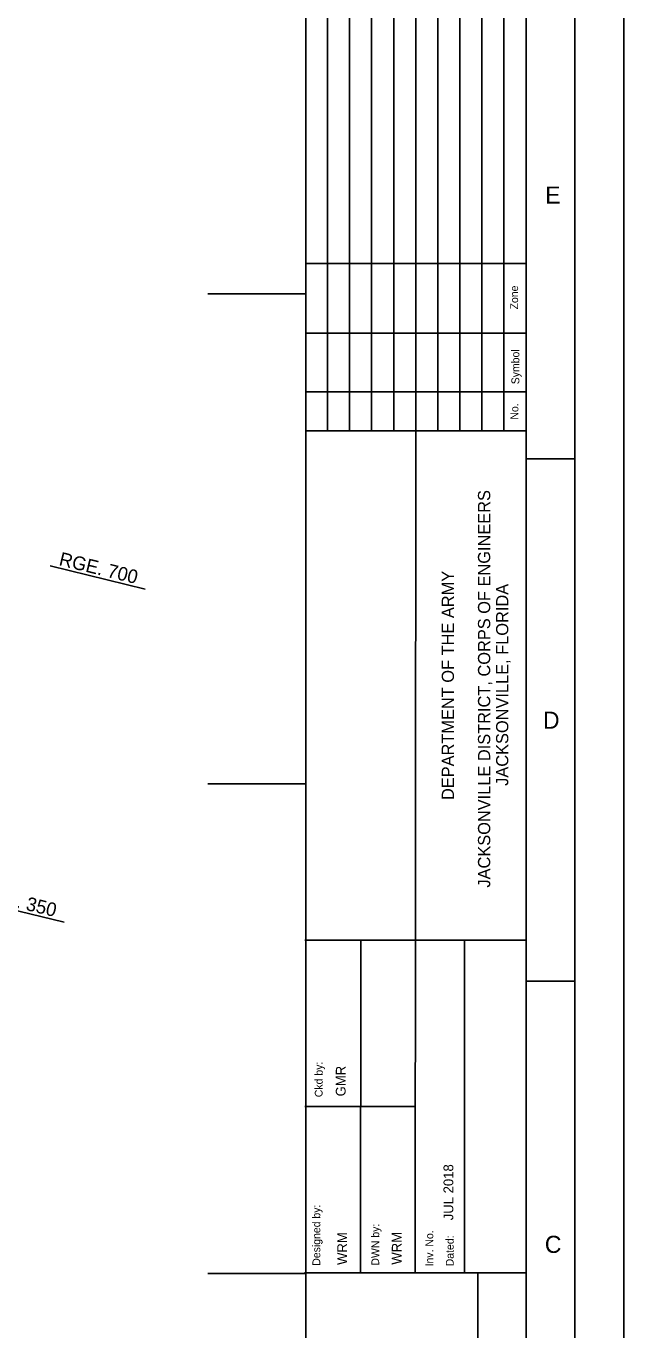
# Model space of a CAD drawing. Extents: x 401290 to 405690, y 1190598 to 1193998.
# Drawn here: x 405079 to 405690, y 1191942 to 1193274 of the extents above; entities that cross this region are included whole.
import ezdxf

# ---------------------------------------------------------------- set-up
doc = ezdxf.new("R2010")
doc.units = 0
for name, color, linetype in [('G-ANNO-NPLT', 7, 'Continuous'), ('G-ANNO-TEXT-DRWG', 7, 'Continuous'), ('G-ANNO-TEXT-PROJ', 7, 'Continuous'), ('G-ANNO-TEXT-TTLB', 7, 'Continuous'), ('G-ANNO-TTLB', 7, 'Continuous'), ('V-ALGN-TEXT', 7, 'Continuous'), ('V-TOPO-COOR-STAT', 7, 'Continuous')]:
    doc.layers.add(name, color=color, linetype=linetype)

msp = doc.modelspace()

# ---------------------------------------------------------------- linework, layer by layer
at = {"layer": 'G-ANNO-NPLT'}
msp.add_lwpolyline([(401290, 1193998.4), (405690, 1193998.4), (405690, 1190598.4), (401290, 1190598.4)], close=True, dxfattribs=at)
at = {"layer": 'G-ANNO-TTLB'}
for p, q in [((405365, 1193898.4), (405365, 1190698.4)), ((405387.3, 1193698.1), (405387.3, 1192860.1)), ((405409.8, 1193698.1), (405409.8, 1192860.1)), ((405432.3, 1193698.1), (405432.3, 1192860.1)), ((405454.8, 1193698.1), (405454.8, 1192860.1)), ((405477.3, 1193698.1), (405477.3, 1192860.1)), ((405499.8, 1193698.1), (405499.8, 1192860.1)), ((405522.3, 1193698.1), (405522.3, 1192860.1)), ((405544.8, 1193698.1), (405544.8, 1192860.1)), ((405567.3, 1193698.1), (405567.3, 1192860.1)), ((405365, 1193031.2), (405590, 1193031.2)), ((405365, 1192960), (405590, 1192960)), ((405365, 1192900), (405590, 1192900)), ((405365, 1192860.1), (405590, 1192860.1)), ((405476.8, 1192000.6), (405477.5, 1192860.1)), ((405477.5, 1192860.1), (405477.5, 1192824.7)), ((405640, 1192831.6), (405590, 1192831.6)), ((405364.2, 1192340.2), (405590, 1192340.2)), ((405420.9, 1192000.6), (405421.1, 1192340.2)), ((405527, 1192340.2), (405527, 1192000.6)), ((405640, 1192298.3), (405590, 1192298.3)), ((405364.2, 1192170.4), (405477, 1192170.4)), ((405363.8, 1192000.6), (405590, 1192000.6)), ((405540.7, 1192000.6), (405540.7, 1191649.2))]:
    msp.add_line(p, q, dxfattribs=at)
for points in [[(401340, 1190648.4), (405640, 1190648.4), (405640, 1193948.4), (401340, 1193948.4)], [(405590, 1193898.4), (401465, 1193898.4), (401465, 1190698.4), (405590, 1190698.4)]]:
    msp.add_lwpolyline(points, close=True, dxfattribs=at)
at = {"layer": 'V-ALGN-TEXT'}
for p, q in [((405103.9, 1192722.4), (405201, 1192698.7)), ((405020.9, 1192382.3), (405118.1, 1192358.6))]:
    msp.add_line(p, q, dxfattribs=at)
at = {"layer": 'V-TOPO-COOR-STAT'}
for p, q in [((405265, 1193000), (405365, 1193000)), ((405265, 1192500), (405365, 1192500)), ((405265, 1192000), (405365, 1192000))]:
    msp.add_line(p, q, dxfattribs=at)

# ---------------------------------------------------------------- texts
at = {"layer": 'G-ANNO-TEXT-DRWG'}
for s, p in [('GMR', (405405.7, 1192180.7)), ('WRM', (405407.2, 1192008.6)), ('WRM', (405462.9, 1192008.9))]:
    msp.add_text(s, height=10, rotation=90, dxfattribs=at).set_placement(p)
at = {"layer": 'G-ANNO-TEXT-PROJ'}
msp.add_text('JUL 2018', height=10, rotation=90, dxfattribs=at).set_placement((405515.7, 1192054.2))
at = {"layer": 'G-ANNO-TEXT-TTLB'}
for s, height, p in [('Zone', 8, (405581.9, 1192984.2)), ('Symbol', 8, (405583.1, 1192907.8)), ('No.', 8, (405582.1, 1192871.7)), ('JACKSONVILLE DISTRICT, CORPS OF ENGINEERS', 12.5, (405553.4, 1192393.9)), ('DEPARTMENT OF THE ARMY', 12.5, (405516.4, 1192483.3)), ('JACKSONVILLE, FLORIDA', 12.5, (405571.9, 1192497.8)), ('Ckd by:', 8, (405382.2, 1192179.9)), ('Designed by:', 8, (405379.8, 1192007.8)), ('DWN by:', 8, (405440, 1192007.9)), ('Inv. No.', 8, (405495.2, 1192007.1)), ('Dated:', 8, (405516.1, 1192007.2))]:
    msp.add_text(s, height=height, rotation=90, dxfattribs=at).set_placement(p)
at = {"layer": 'G-ANNO-TTLB'}
for s, p in [('E', (405609.6, 1193092.2)), ('D', (405607.3, 1192556.1)), ('C', (405609.2, 1192020.9))]:
    msp.add_text(s, height=17.5, dxfattribs=at).set_placement(p)
at = {"layer": 'V-ALGN-TEXT'}
for s, p in [('RGE. 700', (405112.1, 1192723.2)), ('RGE. 350', (405029.1, 1192383.2))]:
    msp.add_text(s, height=13.92, rotation=346.2946, dxfattribs=at).set_placement(p)

doc.saveas('drawing.dxf')
